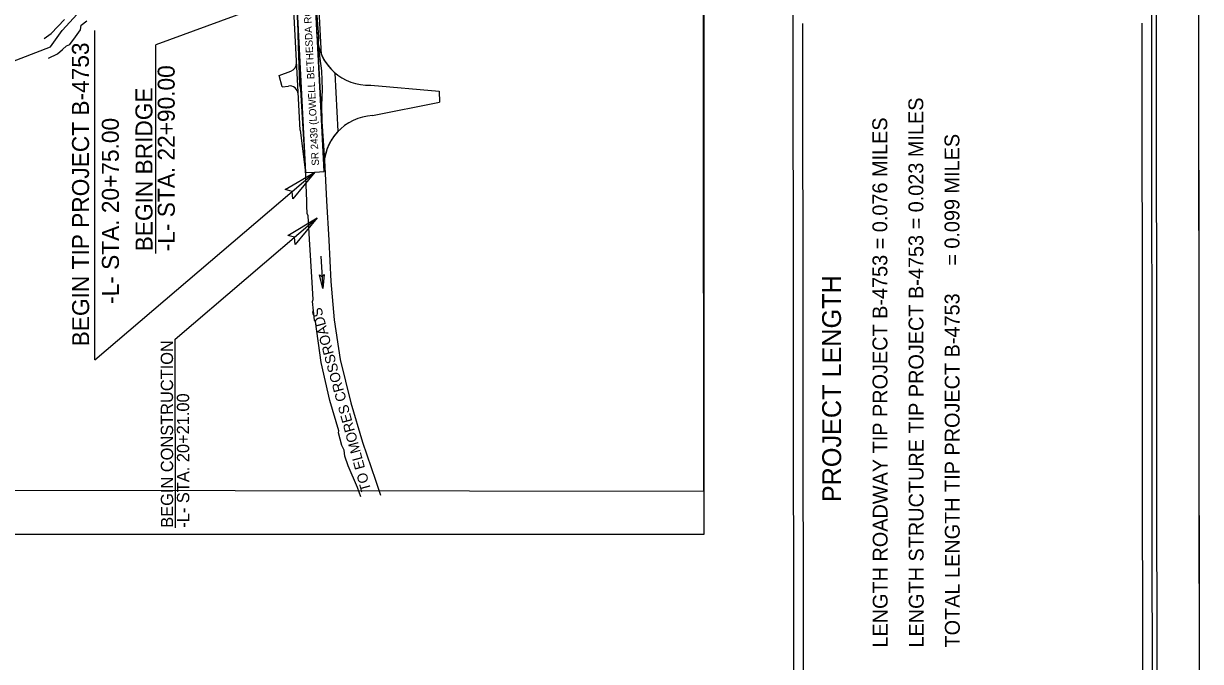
# Model space of a CAD drawing. Extents: x 1372027 to 1374286, y 553832 to 556743.
# Drawn here: x 1373560 to 1374184, y 554446 to 554785 of the extents above; entities that cross this region are included whole.
import ezdxf

# ---------------------------------------------------------------- set-up
doc = ezdxf.new("R2010")
doc.units = 0
for name, color, linetype in [('Default', 7, 'Continuous'), ('Prop Approach Slab', 7, 'Continuous'), ('Prop Approach Slab Hatching', 7, 'Continuous'), ('Prop Dimension', 7, 'Continuous'), ('Prop Dimension Text', 7, 'Continuous'), ('Prop EOT', 7, 'Continuous'), ('Prop Horizontal Alignment Station Label', 7, 'Continuous'), ('Prop North Arrow for Plan Sheets CELL', 7, 'Continuous'), ('Prop Paved Shoulder', 7, 'Continuous'), ('Prop Roadway Bridge', 7, 'Continuous'), ('Prop Shade Light', 7, 'Continuous'), ('Prop Structure Anchor Unit CELL', 7, 'Continuous'), ('Prop Terminator CELL', 7, 'Continuous'), ('Sheet Clip Boundary CELL', 7, 'Continuous'), ('Sheet Layout Plan Border', 7, 'Continuous'), ('Sheet Plan Layout CELL', 7, 'Continuous'), ('Sheet Plot Border Inside CELL', 7, 'Continuous')]:
    doc.layers.add(name, color=color, linetype=linetype)

msp = doc.modelspace()

# ---------------------------------------------------------------- linework, layer by layer
at = {"layer": 'Default'}
msp.add_line((1373717.47, 554661.42), (1373718.56, 554644.26), dxfattribs=at)
at = {"layer": 'Prop Approach Slab'}
msp.add_lwpolyline([(1374161.39, 553845.95), (1374159.91, 555512.45), (1373104.81, 555511.51), (1373106.29, 553845.01)], close=True, dxfattribs=at)
at = {"layer": 'Prop Approach Slab Hatching'}
msp.add_lwpolyline([(1373082.36, 555515.99), (1373083.86, 553831.99), (1374183.84, 553832.97), (1374182.35, 555516.97)], close=True, dxfattribs=at)
at = {"layer": 'Prop Dimension'}
for p, q in [((1373709.4, 554802.64), (1373629.97, 554773.41)), ((1373597.8, 554606.39), (1373597.64, 554781.08)), ((1373630.07, 554662.82), (1373629.97, 554773.41)), ((1373597.8, 554606.39), (1373714.39, 554706.01)), ((1373640.35, 554617.4), (1373715.66, 554681.75)), ((1373640.44, 554517.34), (1373640.35, 554617.4))]:
    msp.add_line(p, q, dxfattribs=at)
at = {"layer": 'Prop Dimension Text'}
msp.add_lwpolyline([(1373448.16, 554513.79), (1373448.16, 555188.2), (1373920.65, 555188.2), (1373920.65, 554513.79)], close=True, dxfattribs=at)
at = {"layer": 'Prop EOT'}
for p, q in [((1373707.12, 554750.7), (1373700.13, 554886)), ((1373715.64, 554777.72), (1373710.02, 554886.51)), ((1373695.5, 554757.24), (1373701.68, 554759.5)), ((1373726.78, 554727.75), (1373725.19, 554758.48)), ((1373697.02, 554751.16), (1373695.5, 554757.24)), ((1373744, 554752.15), (1373780.21, 554748.84)), ((1373697.02, 554751.16), (1373700.36, 554751.64)), ((1373707.12, 554750.7), (1373709.42, 554705.76)), ((1373780.21, 554748.84), (1373780.52, 554743)), ((1373744.83, 554735.98), (1373780.52, 554743)), ((1373709.42, 554705.76), (1373714.39, 554706.01)), ((1373714.39, 554706.01), (1373719.33, 554706.27)), ((1373719.33, 554706.27), (1373719.26, 554707.62))]:
    msp.add_line(p, q, dxfattribs=at)
for centre, radius, start, end in [((1373742.6, 554779.12), 27, 182.95848, 272.95848), ((1373700.14, 554763.73), 4.5, 290.06443, 2.95848), ((1373701, 554747.18), 4.5, 2.95848, 98.15941), ((1373746.23, 554709.01), 27, 92.95848, 182.95848)]:
    msp.add_arc(centre, radius, start, end, dxfattribs=at)
at = {"layer": 'Prop North Arrow for Plan Sheets CELL'}
msp.add_lwpolyline([(1373719.35, 554651.61), (1373718.56, 554644.26), (1373716.8, 554651.49), (1373718.15, 554650.64)], close=True, dxfattribs=at)
at = {"layer": 'Prop Paved Shoulder'}
for p, q in [((1373706.49, 554728.14), (1373698.33, 554885.9)), ((1373717.94, 554768.14), (1373711.81, 554886.6)), ((1373706.49, 554728.14), (1373709.42, 554705.76))]:
    msp.add_line(p, q, dxfattribs=at)
at = {"layer": 'Prop Roadway Bridge'}
for p, q in [((1373968.64, 554064.77), (1373967.37, 555484.77)), ((1373973.35, 554404.78), (1373973.01, 554784.78))]:
    msp.add_line(p, q, dxfattribs=at)
for points in [[(1374158.7, 554009.94), (1374157.38, 555489.94)], [(1374153.35, 554404.94), (1374153.01, 554784.94)]]:
    msp.add_lwpolyline(points, dxfattribs=at)
at = {"layer": 'Prop Shade Light'}
msp.add_line((1373726.78, 554727.75), (1373725.19, 554758.48), dxfattribs=at)
msp.add_lwpolyline([(1373714.34, 554802.89), (1373704.46, 554802.38), (1373707.12, 554750.7), (1373709.42, 554705.76), (1373714.39, 554706.01), (1373719.33, 554706.27), (1373717.01, 554751.21)], close=True, dxfattribs=at)
msp.add_lwpolyline([(1373715.64, 554777.72), (1373717.01, 554751.21), (1373719.26, 554707.62)], dxfattribs=at)
for centre, start, end in [((1373742.6, 554779.12), 182.95848, 229.8538), ((1373746.23, 554709.01), 136.06315, 182.95848)]:
    msp.add_arc(centre, 27, start, end, dxfattribs=at)
at = {"layer": 'Prop Structure Anchor Unit CELL'}
msp.add_line((1374183.84, 553832.97), (1374182.35, 555516.97), dxfattribs=at)
at = {"layer": 'Prop Terminator CELL'}
msp.add_lwpolyline([(1373508.72, 554630.78), (1373513.73, 554667.88), (1373511.28, 554712.53), (1373529.75, 554755.21), (1373574.28, 554772.47), (1373580.36, 554781.04), (1373588.29, 554789.72), (1373590.48, 554804.48), (1373602.72, 554811.26), (1373638.71, 554817.3), (1373685.99, 554822.67), (1373694.48, 554828.39), (1373707.82, 554832.57), (1373716.77, 554835.64)], dxfattribs=at)
for points in [[(1373698.69, 554696.68), (1373714.39, 554706.01), (1373702.71, 554691.82), (1373702.38, 554695.75)], [(1373699.96, 554672.41), (1373715.66, 554681.75), (1373703.98, 554667.56), (1373703.65, 554671.48)]]:
    msp.add_lwpolyline(points, close=True, dxfattribs=at)
at = {"layer": 'Sheet Clip Boundary CELL'}
msp.add_lwpolyline([(1373920.63, 554536.72), (1373920.07, 555166.73), (1373542.74, 555166.39), (1373542.82, 555081.22), (1373447.65, 555081.14), (1373448.5, 554711.84), (1373547.67, 554711.94), (1373547.83, 554537.32)], close=True, dxfattribs=at)
at = {"layer": 'Sheet Layout Plan Border'}
for p, q in [((1373574.57, 554779.47), (1373581.62, 554786.93)), ((1373590.11, 554781.36), (1373590.52, 554783.99)), ((1373590.52, 554783.99), (1373593.55, 554786.13)), ((1373570.93, 554776.87), (1373574.57, 554779.47)), ((1373584.38, 554773.68), (1373587.46, 554777.67)), ((1373587.46, 554777.67), (1373590.11, 554781.36)), ((1373577.85, 554768.64), (1373580.57, 554771.09)), ((1373580.57, 554771.09), (1373582.76, 554772.97)), ((1373582.76, 554772.97), (1373584.38, 554773.68)), ((1373573.1, 554766.46), (1373577.85, 554768.64))]:
    msp.add_line(p, q, dxfattribs=at)
at = {"layer": 'Sheet Plot Border Inside CELL'}
for points in [[(1373717.7, 554605.01), (1373714.78, 554626.79), (1373714.14, 554627.48), (1373713.11, 554637.3), (1373713.51, 554638.48), (1373712.94, 554647.49), (1373711.47, 554670.47), (1373710.73, 554682.74), (1373710.3, 554684.1), (1373710.09, 554688.16), (1373710.1, 554690.71), (1373709.24, 554711.76), (1373708.05, 554731.98), (1373706.91, 554749.71), (1373706.47, 554752.2), (1373705.97, 554762.63), (1373705.75, 554772.65), (1373705.23, 554792.94), (1373703.75, 554811.22)], [(1373714.21, 554811.82), (1373715.02, 554793.47), (1373716.37, 554777.76), (1373716.17, 554772.76), (1373717.82, 554759.68), (1373718.3, 554749.77), (1373717.85, 554741.51), (1373718.04, 554732.79), (1373719.39, 554712.27), (1373720.56, 554690.69), (1373721.68, 554669.89), (1373722.84, 554647.98), (1373724.62, 554627.55), (1373727.82, 554606.64), (1373733.37, 554583.58), (1373739.54, 554562.71), (1373746.42, 554542.5), (1373749.23, 554534.64)], [(1373738.69, 554533.79), (1373737, 554538.6), (1373732.09, 554550.25), (1373730.23, 554555.23), (1373729.93, 554558.51), (1373728.74, 554561.03), (1373726.87, 554567.64), (1373727.12, 554568.74), (1373722.38, 554584.78), (1373717.7, 554605.01)]]:
    msp.add_lwpolyline(points, dxfattribs=at)

# ---------------------------------------------------------------- texts
at = {"layer": 'Default'}
for s, height, rotation, p in [('SR 2439 (LOWELL BETHESDA ROAD)', 3.888, 92.999, (1373716.6, 554709.49)), ('TO ELMORES CROSSROADS', 5.4, 105.24934, (1373744.18, 554537.41))]:
    msp.add_text(s, height=height, rotation=rotation, dxfattribs=at).set_placement(p)
at = {"layer": 'Prop Horizontal Alignment Station Label'}
for s, p in [('LENGTH STRUCTURE TIP PROJECT B-4753 = 0.023 MILES', (1374037.14, 554453.8)), ('LENGTH ROADWAY TIP PROJECT B-4753 = 0.076 MILES', (1374018.02, 554453.78)), ('TOTAL LENGTH TIP PROJECT B-4753     = 0.099 MILES', (1374056.27, 554453.82))]:
    msp.add_text(s, height=7.8751, rotation=90.05095, dxfattribs=at).set_placement(p)
at = {"layer": 'Prop Roadway Bridge'}
msp.add_text('PROJECT LENGTH', height=9.9996, rotation=90.05095, dxfattribs=at).set_placement((1373993.37, 554530.9))
at = {"layer": 'Sheet Plan Layout CELL'}
for s, height, p in [('BEGIN TIP PROJECT B-4753', 9, (1373594.71, 554613.56)), ('-L- STA. 22+90.00', 9, (1373640.12, 554663.97)), ('BEGIN BRIDGE', 9, (1373628.32, 554663.96)), ('-L- STA. 20+75.00 ', 9, (1373610.5, 554636.06)), ('BEGIN CONSTRUCTION', 6.5, (1373639.24, 554517.34)), ('-L- STA. 20+21.00', 6.5, (1373647.76, 554517.35))]:
    msp.add_text(s, height=height, rotation=90.05095, dxfattribs=at).set_placement(p)

doc.saveas('drawing.dxf')
